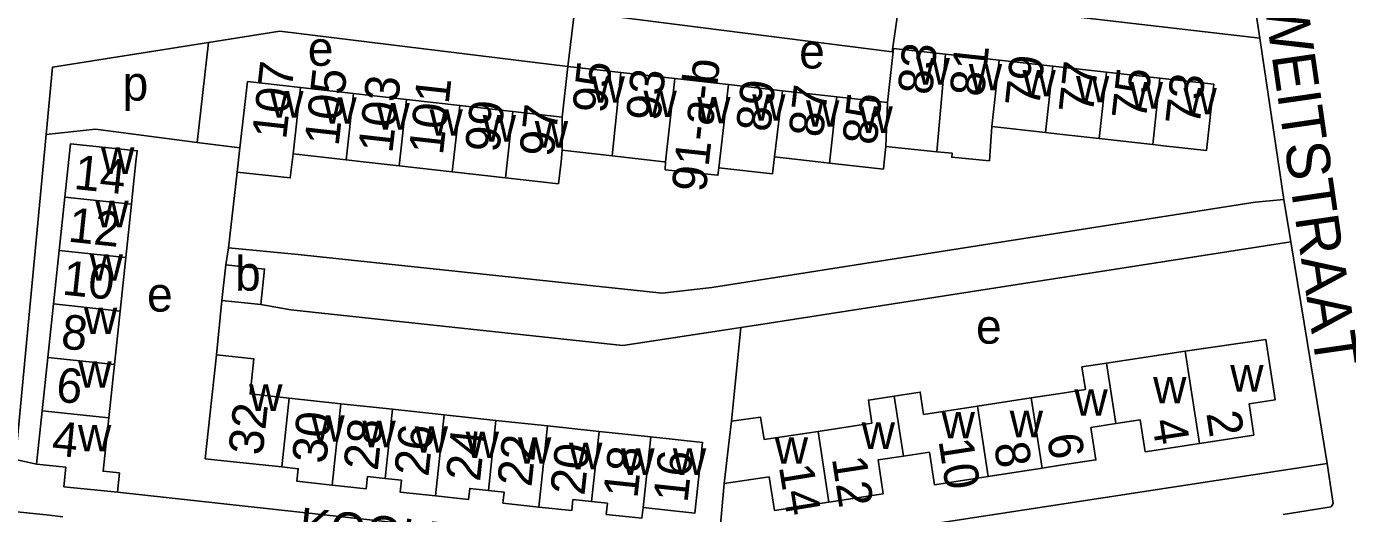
# Model space of a CAD drawing. Extents: x 161936 to 163647, y 386450 to 388633.
# Drawn here: x 162379.9 to 162533, y 387459.2 to 387515.7 of the extents above; entities that cross this region are included whole.
import ezdxf

# ---------------------------------------------------------------- set-up
doc = ezdxf.new("R2010")
doc.units = 0
for name, color, linetype in [('BLT_Basislijn', 7, 'Continuous'), ('BLT_Bebouwing', 7, 'Continuous'), ('BLT_Centroide', 7, 'Continuous'), ('BLT_Huisnummer', 7, 'Continuous'), ('BLT_Huisnummer_ tussenligend', 7, 'Continuous'), ('BLT_Huisnummer_reeks', 7, 'Continuous'), ('BLT_Onderverdeling_panden', 7, 'Continuous'), ('BLT_Straatnaam', 7, 'Continuous'), ('BLT_Straatnaam_verkleind', 7, 'Continuous')]:
    doc.layers.add(name, color=color, linetype=linetype)

msp = doc.modelspace()

# ---------------------------------------------------------------- linework, layer by layer
at = {"layer": 'BLT_Basislijn'}
for p, q in [((162522.87, 387514.31), (162522.11, 387519.43)), ((162399.71, 387502.25), (162401.01, 387513.83)), ((162525.64, 387495.62), (162522.87, 387514.31)), ((162387.93, 387503.77), (162399.71, 387502.25)), ((162399.71, 387502.25), (162404.67, 387501.61)), ((162404.36, 387498.81), (162403.36, 387490.03)), ((162525.64, 387495.62), (162526.47, 387490.71)), ((162530.66, 387465.03), (162526.47, 387490.71)), ((162403.36, 387490.03), (162403.03, 387488.05)), ((162402.59, 387483.94), (162401.95, 387477.63)), ((162462.72, 387480.78), (162460.22, 387480.4)), ((162461.63, 387469.95), (162462.72, 387480.78)), ((162460.05, 387454.24), (162530.66, 387465.03)), ((162460.79, 387462.71), (162460.05, 387454.24))]:
    msp.add_line(p, q, dxfattribs=at)
for points in [[(162442.69, 387511.03), (162443.45, 387517.42), (162480.25, 387512.74), (162481.2, 387519.2), (162522.87, 387514.31)], [(162382.22, 387503.16), (162382.96, 387510.97), (162401.01, 387513.83)], [(162401.01, 387513.83), (162409.3, 387515.14), (162442.69, 387511.03)], [(162382.22, 387503.16), (162378.64, 387465.49), (162381.09, 387464.96)], [(162387.93, 387503.77), (162382.22, 387503.16)], [(162459.36, 387485.44), (162522.35, 387495.32), (162525.64, 387495.62)], [(162526.47, 387490.71), (162464.78, 387481.09), (162462.72, 387480.78)], [(162403.36, 387490.03), (162411.41, 387489.24), (162453.61, 387484.77), (162459.36, 387485.44)], [(162407.09, 387483.46), (162410.58, 387482.84), (162449.04, 387478.7), (162460.22, 387480.4)], [(162525.58, 387459.13), (162531.12, 387460.02), (162531.39, 387460.41), (162530.66, 387465.03)], [(162460.05, 387454.24), (162459.5, 387454.15), (162390.49, 387461.73)], [(162384.13, 387458.87), (162382.58, 387459.04), (162377.68, 387459.55), (162372.37, 387413.31)]]:
    msp.add_lwpolyline(points, dxfattribs=at)
at = {"layer": 'BLT_Bebouwing'}
for p, q in [((162486.45, 387512.45), (162492.66, 387511.76)), ((162442.03, 387505.18), (162442.69, 387511.03)), ((162442.69, 387511.03), (162448.8, 387510.34)), ((162492.66, 387511.76), (162498.88, 387511.07)), ((162498.88, 387511.07), (162505.09, 387510.37)), ((162404.67, 387501.61), (162405.53, 387509.29)), ((162405.53, 387509.29), (162411.69, 387508.59)), ((162448.8, 387510.34), (162455.06, 387509.64)), ((162455.06, 387509.64), (162461.31, 387508.94)), ((162505.09, 387510.37), (162511.3, 387509.68)), ((162411.69, 387508.59), (162417.84, 387507.9)), ((162417.84, 387507.9), (162423.99, 387507.21)), ((162461.31, 387508.94), (162467.57, 387508.23)), ((162467.57, 387508.23), (162473.83, 387507.53)), ((162473.83, 387507.53), (162479.71, 387506.87)), ((162423.99, 387507.21), (162430.15, 387506.52)), ((162430.15, 387506.52), (162436.3, 387505.83)), ((162436.3, 387505.83), (162442.03, 387505.18)), ((162491.83, 387504.07), (162498.05, 387503.38)), ((162404.67, 387501.61), (162404.36, 387498.81)), ((162479.54, 387501.76), (162485.42, 387501.16)), ((162504.26, 387502.69), (162510.48, 387501.99)), ((162410.82, 387500.92), (162416.98, 387500.22)), ((162442.02, 387501.33), (162447.82, 387500.68)), ((162423.13, 387499.53), (162429.28, 387498.84)), ((162429.28, 387498.84), (162435.44, 387498.15)), ((162383.73, 387489.71), (162384.39, 387495.9)), ((162392.1, 387495.08), (162391.44, 387488.89)), ((162383.07, 387483.52), (162383.73, 387489.71)), ((162391.44, 387488.89), (162390.78, 387482.7)), ((162402.59, 387483.94), (162403.03, 387488.05)), ((162382.41, 387477.33), (162383.07, 387483.52)), ((162402.59, 387483.94), (162407.09, 387483.46)), ((162390.78, 387482.7), (162390.12, 387476.51)), ((162381.75, 387471.14), (162382.41, 387477.33)), ((162390.12, 387476.51), (162389.46, 387470.32)), ((162416.37, 387471.96), (162410.38, 387472.6)), ((162496.38, 387472.64), (162490.14, 387471.69)), ((162381.09, 387464.96), (162381.75, 387471.14)), ((162422.36, 387471.32), (162416.37, 387471.96)), ((162428.34, 387470.68), (162422.36, 387471.32)), ((162434.33, 387470.03), (162428.34, 387470.68)), ((162440.32, 387469.39), (162434.33, 387470.03)), ((162446.31, 387468.75), (162440.32, 387469.39)), ((162452.29, 387468.11), (162446.31, 387468.75)), ((162497.63, 387464.49), (162491.39, 387463.53))]:
    msp.add_line(p, q, dxfattribs=at)
for points in [[(162479.71, 387506.87), (162480.41, 387513.12), (162486.45, 387512.45)], [(162510.48, 387501.99), (162511.72, 387501.86), (162516.69, 387501.3), (162517.54, 387508.99), (162511.3, 387509.68)], [(162485.42, 387501.16), (162487.22, 387500.98), (162487.16, 387500.52), (162491.54, 387500.11), (162491.83, 387504.07)], [(162498.05, 387503.38), (162500, 387503.16), (162504.26, 387502.69)], [(162384.39, 387495.9), (162385.05, 387502.09), (162392.76, 387501.27), (162392.62, 387500), (162392.23, 387496.3), (162392.1, 387495.08)], [(162473, 387499.85), (162479.25, 387499.15), (162479.35, 387500), (162479.54, 387501.76)], [(162410.82, 387500.92), (162410.51, 387498.12), (162404.36, 387498.81)], [(162416.98, 387500.22), (162418.96, 387500), (162423.13, 387499.53)], [(162435.44, 387498.15), (162441.59, 387497.45), (162441.88, 387500), (162442.02, 387501.33)], [(162447.82, 387500.68), (162453.84, 387500), (162454.01, 387499.98)], [(162454.01, 387499.98), (162453.97, 387499.07), (162460.07, 387498.43), (162460.17, 387499.29)], [(162460.17, 387499.29), (162466.38, 387498.59), (162466.61, 387500.57)], [(162466.61, 387500.57), (162471.7, 387500), (162473, 387499.85)], [(162407.09, 387483.46), (162407.52, 387487.57), (162403.03, 387488.05)], [(162515.87, 387467.37), (162522.17, 387468.33), (162521.62, 387471.94), (162524.64, 387472.41), (162523.57, 387479.4), (162514.23, 387478.05)], [(162409.53, 387464.64), (162403.54, 387465.28), (162400.65, 387465.59), (162401.19, 387470.56), (162401.95, 387477.63)], [(162401.95, 387477.63), (162406.29, 387477.16), (162405.85, 387473.09), (162410.38, 387472.6)], [(162514.23, 387478.05), (162505.12, 387476.66)], [(162505.12, 387476.66), (162502.25, 387476.22), (162502.65, 387473.61), (162500, 387473.2), (162496.38, 387472.64)], [(162480.51, 387472.85), (162477.51, 387472.39), (162477.92, 387469.72), (162471.67, 387468.76)], [(162490.14, 387471.69), (162483.9, 387470.73), (162483.51, 387473.31), (162480.51, 387472.85)], [(162389.46, 387470.32), (162388.8, 387464.13), (162390.71, 387463.95), (162390.49, 387461.73)], [(162460.79, 387462.71), (162461.36, 387467.68), (162461.63, 387469.95)], [(162471.67, 387468.76), (162465.43, 387467.8), (162465.01, 387470.4), (162461.63, 387469.95)], [(162506.2, 387469.65), (162503.29, 387469.2), (162503.87, 387465.45), (162500, 387464.86), (162497.63, 387464.49)], [(162515.87, 387467.37), (162509.57, 387466.4), (162509.01, 387470.08), (162506.2, 387469.65)], [(162452.29, 387468.11), (162458.28, 387467.47), (162457.93, 387464.25), (162457.4, 387459.28), (162451.41, 387459.92)], [(162491.39, 387463.53), (162485.15, 387462.58), (162484.57, 387466.36), (162481.57, 387465.9)], [(162390.49, 387461.73), (162384.27, 387462.34), (162384.49, 387464.6), (162381.09, 387464.96)], [(162415.36, 387462.54), (162411.28, 387462.97), (162411.43, 387464.43), (162409.53, 387464.64)], [(162481.57, 387465.9), (162478.62, 387465.45), (162479.22, 387461.53), (162472.93, 387460.57)], [(162421.5, 387463.29), (162419.46, 387463.51), (162419.31, 387462.11), (162415.36, 387462.54)], [(162427.34, 387461.29), (162423.23, 387461.73), (162423.38, 387463.09), (162421.5, 387463.29)], [(162472.93, 387460.57), (162466.63, 387459.6), (162465.99, 387463.48), (162460.79, 387462.71)], [(162433.46, 387461.91), (162431.3, 387462.15), (162431.16, 387460.88), (162427.34, 387461.29)], [(162439.31, 387459.98), (162435.14, 387460.43), (162435.28, 387461.72), (162433.46, 387461.91)], [(162445.43, 387460.63), (162443.26, 387460.86), (162443.12, 387459.57), (162439.31, 387459.98)], [(162451.41, 387459.92), (162451.24, 387458.69), (162447.12, 387459.13), (162447.26, 387460.43), (162445.43, 387460.63)]]:
    msp.add_lwpolyline(points, dxfattribs=at)
at = {"layer": 'BLT_Onderverdeling_panden'}
for p, q in [((162491.83, 387504.07), (162492.66, 387511.76)), ((162498.05, 387503.38), (162498.88, 387511.07)), ((162447.82, 387500.68), (162448.8, 387510.34)), ((162454.01, 387499.98), (162455.06, 387509.64)), ((162504.26, 387502.69), (162505.09, 387510.37)), ((162510.48, 387501.99), (162511.3, 387509.68)), ((162410.82, 387500.92), (162411.69, 387508.59)), ((162416.98, 387500.22), (162417.84, 387507.9)), ((162460.17, 387499.29), (162461.31, 387508.94)), ((162466.61, 387500.57), (162467.57, 387508.23)), ((162473, 387499.85), (162473.83, 387507.53)), ((162423.13, 387499.53), (162423.99, 387507.21)), ((162429.28, 387498.84), (162430.15, 387506.52)), ((162479.71, 387506.87), (162479.54, 387501.76)), ((162435.44, 387498.15), (162436.3, 387505.83)), ((162442.03, 387505.18), (162442.02, 387501.33)), ((162392.1, 387495.08), (162384.39, 387495.9)), ((162391.44, 387488.89), (162383.73, 387489.71)), ((162390.78, 387482.7), (162383.07, 387483.52)), ((162390.12, 387476.51), (162382.41, 387477.33)), ((162515.87, 387467.37), (162514.23, 387478.05)), ((162505.12, 387476.66), (162506.2, 387469.65)), ((162410.38, 387472.6), (162409.53, 387464.64)), ((162480.51, 387472.85), (162481.57, 387465.9)), ((162497.63, 387464.49), (162496.38, 387472.64)), ((162389.46, 387470.32), (162381.75, 387471.14)), ((162416.37, 387471.96), (162415.36, 387462.54)), ((162422.36, 387471.32), (162421.5, 387463.29)), ((162491.39, 387463.53), (162490.14, 387471.69)), ((162428.34, 387470.68), (162427.34, 387461.29)), ((162434.33, 387470.03), (162433.46, 387461.91)), ((162440.32, 387469.39), (162439.31, 387459.98)), ((162446.31, 387468.75), (162445.43, 387460.63)), ((162452.29, 387468.11), (162451.41, 387459.92)), ((162472.93, 387460.57), (162471.67, 387468.76))]:
    msp.add_line(p, q, dxfattribs=at)
msp.add_lwpolyline([(162485.42, 387501.16), (162486.45, 387512.45)], dxfattribs=at)

# ---------------------------------------------------------------- texts
at = {"layer": 'BLT_Centroide'}
for s, p in [('e', (162412.53, 387511.12)), ('e', (162469.48, 387510.81)), ('w', (162483.08, 387508.94)), ('w', (162489.14, 387508.27)), ('w', (162495.36, 387507.58)), ('p', (162391.07, 387507.09)), ('w', (162445.42, 387506.83)), ('w', (162501.56, 387506.88)), ('w', (162507.78, 387506.17)), ('w', (162408.17, 387505.11)), ('w', (162451.44, 387505.17)), ('w', (162457.66, 387504.45)), ('w', (162464.03, 387504.75)), ('w', (162514.02, 387505.48)), ('w', (162414.33, 387504.41)), ('w', (162420.48, 387503.72)), ('w', (162426.64, 387503.02)), ('w', (162470.28, 387504.05)), ('w', (162476.47, 387503.34)), ('w', (162432.8, 387502.33)), ('w', (162438.84, 387501.64)), ('w', (162388.57, 387498.59)), ('w', (162387.91, 387492.41)), ('w', (162387.26, 387486.22)), ('b', (162404.11, 387485.07)), ('e', (162393.9, 387482.64)), ('w', (162386.59, 387480.03)), ('e', (162489.98, 387478.92)), ('w', (162385.93, 387473.81)), ('w', (162519.44, 387473.36)), ('w', (162405.73, 387471.12)), ('w', (162510.5, 387472)), ('w', (162501.38, 387470.56)), ('w', (162485.99, 387467.94)), ('w', (162493.88, 387468.08)), ('w', (162385.89, 387466.44)), ('w', (162412.95, 387467.55)), ('w', (162418.86, 387466.92)), ('w', (162424.92, 387466.28)), ('w', (162476.72, 387466.72)), ('w', (162430.83, 387465.66)), ('w', (162436.89, 387465)), ('w', (162466.65, 387465)), ('w', (162442.81, 387464.36)), ('w', (162448.86, 387463.7)), ('w', (162454.84, 387463.7))]:
    msp.add_text(s, height=4, dxfattribs=at).set_placement(p)
at = {"layer": 'BLT_Huisnummer'}
for s, rotation, p in [('81', 83.8468, (162490.87, 387507.43)), ('107', 83.5796, (162410.02, 387502.5)), ('93', 83.8324, (162453.37, 387504.62)), ('77', 83.8536, (162503.52, 387505.47)), ('101', 83.5804, (162428.19, 387500.69)), ('89', 83.8348, (162466.12, 387503.36)), ('73', 83.6418, (162515.88, 387504.09)), ('85', 83.5841, (162478.43, 387501.84)), ('97', 83.6028, (162441, 387500.47)), ('14', 353.9168, (162385.32, 387496.86)), ('8', 353.9152, (162383.83, 387478.39)), ('32', 83.8817, (162407.29, 387465.89)), ('2', 278.7193, (162516.66, 387470.86)), ('4', 354.4262, (162382.77, 387466)), ('28', 83.8825, (162420.63, 387464.11)), ('24', 83.8783, (162432.49, 387462.86)), ('6', 278.7303, (162498.19, 387468.26)), ('20', 83.8798, (162444.59, 387461.24)), ('16', 83.8812, (162456.54, 387460.41)), ('10', 278.7262, (162485.62, 387467.69)), ('14', 279.2608, (162467.12, 387464.68))]:
    msp.add_text(s, height=4, rotation=rotation, dxfattribs=at).set_placement(p)
at = {"layer": 'BLT_Huisnummer_ tussenligend'}
for s, rotation, p in [('83', 83.8468, (162484.85, 387507.64)), ('79', 83.8536, (162497.3, 387506.22)), ('105', 83.5804, (162416.1, 387501.72)), ('95', 83.8324, (162447.15, 387505.52)), ('75', 83.6418, (162509.66, 387504.74)), ('103', 83.5804, (162422.33, 387500.9)), ('87', 83.5841, (162472.21, 387502.73)), ('99', 83.6028, (162434.7, 387500.97)), ('12', 353.9152, (162384.65, 387490.76)), ('10', 353.9152, (162383.98, 387484.62)), ('6', 354.4262, (162383.26, 387472.22)), ('30', 83.8825, (162414.65, 387464.92)), ('26', 83.8783, (162426.51, 387463.43)), ('4', 278.7193, (162510.35, 387469.97)), ('22', 83.8798, (162438.45, 387462.24)), ('18', 83.8812, (162450.73, 387460.91)), ('8', 278.7303, (162492.05, 387467.26)), ('12', 278.7262, (162473.26, 387465.63))]:
    msp.add_text(s, height=4, rotation=rotation, dxfattribs=at).set_placement(p)
at = {"layer": 'BLT_Huisnummer_reeks'}
msp.add_text('91-a-b', height=4, rotation=83.8348, dxfattribs=at).set_placement((162458.66, 387496.39))
at = {"layer": 'BLT_Straatnaam'}
msp.add_text('BOEKWEITSTRAAT', height=5, rotation=278.2054, dxfattribs=at).set_placement((162520.68, 387536.97))
at = {"layer": 'BLT_Straatnaam_verkleind'}
msp.add_text('KOOLZAADPAD', height=4, rotation=353.8996, dxfattribs=at).set_placement((162411.36, 387455.98))

doc.saveas('drawing.dxf')
